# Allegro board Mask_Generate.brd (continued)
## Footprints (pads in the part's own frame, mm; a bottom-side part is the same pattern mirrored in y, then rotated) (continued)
NC06-4
  rect 1.27x0.635 smd: 1(-2.857,1.905) 2(-2.857,0.635) 3(-2.857,-0.635) 4(-2.857,-1.905) 5(2.857,-1.905) 6(2.857,-0.635) 7(2.857,0.635) 8(2.857,1.905)
QUA02BSMD
  rect 1.27x1.6 smd: 1(-1.27,0) 2(1.27,0)
SO08
  rect 1.27x0.635 smd: 1(-2.857,1.905) 2(-2.857,0.635) 3(-2.857,-0.635) 4(-2.857,-1.905) 5(2.857,-1.905) 6(2.857,-0.635) 7(2.857,0.635) 8(2.857,1.905)
SO14
  rect 1.27x0.635 smd: 1(-2.857,3.81) 2(-2.857,2.54) 3(-2.857,1.27) 4(-2.857,0) 5(-2.857,-1.27) 6(-2.857,-2.54) 7(-2.857,-3.81) 8(2.857,-3.81) 9(2.857,-2.54) 10(2.857,-1.27) 11(2.857,0) 12(2.857,1.27) 13(2.857,2.54) 14(2.857,3.81)
SO16B
  rect 1.27x0.635 smd: 1(-4.763,4.445) 2(-4.763,3.175) 3(-4.763,1.905) 4(-4.763,0.635) 5(-4.763,-0.635) 6(-4.763,-1.905) 7(-4.763,-3.175) 8(-4.763,-4.445) 9(4.763,-4.445) 10(4.763,-3.175) 11(4.763,-1.905) 12(4.763,-0.635) 13(4.763,0.635) 14(4.763,1.905) 15(4.763,3.175) 16(4.763,4.445)
SOT23B
  rect 0.508x0.432 smd: 1(-0.889,0.94) 2(-0.889,-0.94) 3(0.889,0)
SOT223-5
  rect 1.27x0.635 smd: 1(-2.477,1.27) 2(-2.477,-1.27) 3(2.477,1.27) 4(2.477,0) 5(2.477,-1.27)
SQU04B
  rect 1.27x0.635 smd: 1(-2.857,1.905) 2(-2.857,-1.905) 3(2.857,-1.905) 4(2.857,1.905)
TAJA
  rect 1.575x1.016 smd: 1(-1.968,0) 2(1.968,0)
TAJC
  rect 2.032x2.032 smd: 1(-2.223,0) 2(2.223,0)
TQFP64D
  rect 0.305x0.914 smd: 1(-0.4,7.429) 2(-1.2,7.429) 3(-2,7.429) 4(-2.8,7.429) 5(-3.6,7.429) 6(-4.401,7.429) 7(-5.201,7.429) 8(-6.001,7.429) 25(-6.001,-7.429) 26(-5.201,-7.429) 27(-4.401,-7.429) 28(-3.6,-7.429) 29(-2.8,-7.429) 30(-2,-7.429) 31(-1.2,-7.429) 32(-0.4,-7.429) 33(0.4,-7.429) 34(1.2,-7.429) 35(2,-7.429) 36(2.8,-7.429) 37(3.6,-7.429) 38(4.401,-7.429) 39(5.201,-7.429) 40(6.001,-7.429) 57(6.001,7.429) 58(5.201,7.429) 59(4.401,7.429) 60(3.6,7.429) 61(2.8,7.429) 62(2,7.429) 63(1.2,7.429) 64(0.4,7.429)
  rect 0.914x0.305 smd: 9(-7.429,6.001) 10(-7.429,5.201) 11(-7.429,4.401) 12(-7.429,3.6) 13(-7.429,2.8) 14(-7.429,2) 15(-7.429,1.2) 16(-7.429,0.4) 17(-7.429,-0.4) 18(-7.429,-1.2) 19(-7.429,-2) 20(-7.429,-2.8) 21(-7.429,-3.6) 22(-7.429,-4.401) 23(-7.429,-5.201) 24(-7.429,-6.001) 41(7.429,-6.001) 42(7.429,-5.201) 43(7.429,-4.401) 44(7.429,-3.6) 45(7.429,-2.8) 46(7.429,-2) 47(7.429,-1.2) 48(7.429,-0.4) 49(7.429,0.4) 50(7.429,1.2) 51(7.429,2) 52(7.429,2.8) 53(7.429,3.6) 54(7.429,4.401) 55(7.429,5.201) 56(7.429,6.001)
TSSOP56A
  rect 1.651x0.406 smd: 1(-5.639,9.601) 2(-5.639,8.801) 3(-5.639,8.001) 4(-5.639,7.201) 5(-5.639,6.401) 6(-5.639,5.601) 7(-5.639,4.801) 8(-5.639,4) 9(-5.639,3.2) 10(-5.639,2.4) 11(-5.639,1.6) 12(-5.639,0.8) 13(-5.639,0) 14(-5.639,-0.8) 15(-5.639,-1.6) 16(-5.639,-2.4) 17(-5.639,-3.2) 18(-5.639,-4) 19(-5.639,-4.801) 20(-5.639,-5.601) 21(-5.639,-6.401) 22(-5.639,-7.201) 23(-5.639,-8.001) 24(-5.639,-8.801) 25(-5.639,-9.601) 26(-5.639,-10.401) 27(-5.639,-11.201) 28(-5.639,-12.002) 29(5.639,-12.002) 30(5.639,-11.201) 31(5.639,-10.401) 32(5.639,-9.601) 33(5.639,-8.801) 34(5.639,-8.001) 35(5.639,-7.201) 36(5.639,-6.401) 37(5.639,-5.601) 38(5.639,-4.801) 39(5.639,-4) 40(5.639,-3.2) 41(5.639,-2.4) 42(5.639,-1.6) 43(5.639,-0.8) 44(5.639,0) 45(5.639,0.8) 46(5.639,1.6) 47(5.639,2.4) 48(5.639,3.2) 49(5.639,4) 50(5.639,4.801) 51(5.639,5.601) 52(5.639,6.401) 53(5.639,7.201) 54(5.639,8.001) 55(5.639,8.801) 56(5.639,9.601)
WWS02
  rect 1.118x1.829 smd: 1(-1.968,0) 2(1.968,0)

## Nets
GND: C61.2 C62.2 C63.2 C64.2 C65.2 C66.2 C67.2 C68.2 C69.2 C72.2 C73.2 C74.2 C75.2 C76.2 C77.2 C78.2 C79.2 C80.2 C81.2 C82.2 C83.2 C84.2 C85.2 C86.2 C87.2 C88.2 C89.2 C90.2 C91.2 C92.2 C93.2 C94.2 C95.2 C96.2 C97.2 C98.2 C99.2 C100.2 C101.2 C102.2 C103.2 C104.2 C105.2 C106.2 C107.2 C108.2 C109.2 C110.2 C111.2 C112.2 C113.2 C114.2 C115.2 C116.2 C117.2 C118.2 C119.2 C120.2 C121.2 C122.2 C123.2 C124.2 C125.2 C126.2 C127.2 C207.2 C208.2 C209.2 C210.2 C211.2 C212.2 C213.2 C214.2 C215.2 C216.2 C217.2 C219.2 C220.2 C221.2 C224.2 C225.2 C226.2 C227.2 C228.2 C229.2 C233.2 C234.2 C235.2 C236.2 C237.2 C238.2 C239.2 C240.2 C241.2 C242.2 C243.2 C244.2 C245.2 C246.2 C247.2 C248.2 C249.2 C250.2 C251.2 C252.2 C253.2 C254.2 C255.2 C256.2 C259.2 C260.2 C261.2 C262.2 C263.2 C264.2 C265.2 C266.2 C267.2 C268.2 C269.2 C270.2 C271.2 C272.2 C273.2 C274.2 C275.2 C276.2 C277.2 C278.2 C279.2 C280.2 C281.2 C282.2 C283.2 C284.2 C285.2 C286.2 C287.2 C288.2 C289.2 C290.2 C291.2 C292.2 C293.2 CF1.2(GND) CF2.2(GND) CF3.2(GND) CF4.3 CF5.2(GND) CF6.2(GND) CF7.2(GND) CF8.2(GND) CN2.3 CN2.11 CN2.18 CN2.26 CN2.34 CN2.42 CN2.50 CN2.58 CN2.66 CN2.74 CN2.81 CN2.89 CN2.93 CN2.97 CN2.100 CN2.107 CN2.116 CN2.119 CN2.124 CN2.129 CN2.132 CN2.139 CN2.140 CN2.145 CN2.149 CN2.152 CN2.159 CN2.160 CN2.169 CN2.176 CN2.177 CN2.181 CN2.182 CN2.183 CN4.2 CN4.3(VSS_DBL) CN5.1(VSS_VDL_FWSL_VCL) CN5.10 CN5.13 CN5.16 CN5.19 CN5.22 CN5.25 CN5.28 Q1.2(E) Q3.2(S) R57.2 R61.2 R62.1 R63.1 R64.2 R93.1 R94.1 R95.1 R99.2 R106.2 R107.2 R109.2 R134.1 R135.1 R136.2 R137.2 R138.1 R139.1 R144.2 R151.1 R154.2 R155.2 R156.2 R157.2 R158.2 R159.2 R160.2 R161.2 R162.2 R163.2 R164.2 R165.2 R166.2 R167.2 R168.2 R171.1 R172.1 R173.1 R176.1 R177.1 R182.1 R183.1 R186.2 R199.2 R201.2 R203.2 R205.2 R212.2 R214.2 R215.1 U2.4 U2.9 U2.15 U2.20 U2.27 U2.31 U2.36 U2.41 U2.47 U3.A3 U3.A7 U3.A11 U3.A15 U3.A19 U3.A23 U3.A27 U3.AA1 U3.AA4 U3.AA8 U3.AA29 U3.AB6 U3.AB9 U3.AB10 U3.AB12 U3.AB13 U3.AB14 U3.AB15 U3.AB16 U3.AB19 U3.AB22 U3.AC1 U3.AC4 U3.AC18 U3.AC20 U3.AC21 U3.AC23 U3.AC26 U3.AD6 U3.AD8 U3.AD10 U3.AD12 U3.AD14 U3.AD16 U3.AD19 U3.AD22 U3.AE1 U3.AE4 U3.AE18 U3.AE20 U3.AE29 U3.AF5 U3.AF7 U3.AF9 U3.AF11 U3.AF13 U3.AF15 U3.AF17 U3.AF19 U3.AF21 U3.AF25 U3.AG1 U3.AG18 U3.AG20 U3.AG22 U3.AH19 U3.AH21 U3.AH23 U3.AJ3 U3.AJ5 U3.AJ7 U3.AJ9 U3.AJ11 U3.AJ13 U3.AJ15 U3.AJ17 U3.AJ27 U3.D5 U3.D9 U3.D13 U3.D17 U3.D21 U3.E1 U3.E4 U3.E26 U3.E29 U3.F8 U3.F12 U3.F16 U3.F20 U3.F24 U3.G26 U3.H9 U3.H11 U3.H13 U3.H15 U3.H17 U3.H19 U3.H21 U3.J1 U3.J4 U3.J6 U3.J22 U3.J26 U3.J29 U3.K5 U3.K7 U3.K27 U3.L1 U3.L4 U3.L6 U3.L8 U3.L22 U3.L24 U3.L26 U3.M23 U3.N1 U3.N4 U3.N8 U3.N13 U3.N15 U3.N17 U3.N22 U3.N29 U3.P6 U3.P8 U3.P14 U3.P16 U3.R1 U3.R4 U3.R13 U3.R15 U3.R17 U3.R26 U3.T6 U3.T8 U3.T14 U3.T16 U3.T22 U3.U1 U3.U4 U3.U15 U3.U29 U3.V6 U3.V8 U3.V22 U3.W1 U3.W4 U3.W8 U3.W26 U3.Y6 U3.Y22 U4.2 U5.A1 U5.A23 U5.AC1 U5.AC23 U5.E5 U5.E7 U5.E9 U5.E11 U5.E13 U5.E15 U5.E19 U5.G5(VSS_9) U5.G19 U5.J5 U5.J19 U5.K12 U5.K13 U5.L5 U5.L12 U5.L13 U5.L19 U5.M12 U5.M13 U5.N5 U5.N12 U5.N13 U5.N19 U5.P12 U5.P13 U5.R5 U5.R19 U5.U5 U5.U19 U5.U22 U5.W5 U5.W9 U5.W11 U5.W14 U5.W16 U5.W17 U5.W19 U6.1 U6.4 U6.7 U7.1 U7.2 U7.4 U7.5 U7.7 U8.6 U8.7 U8.8 U8.16 U8.17 U8.20 U8.26 U8.32 U8.48 U8.64 U10.5 U11.5 U12.5
GND_AMCH: C70.2 C71.2 U3.U13 U3.U17
GND_DVI: CF4.1 ST1.15
GND_VID: C218.2 C223.2 C257.2 C258.2 CN6.1 CN6.2 JP1.2 R189.2 R190.2 R191.2 R215.2 ST1.C5 ST1.C6 U5.AA21 U5.AA22 U5.U20 U5.W20 U5.W22 U9.4 U9.13
A_CLKX1: C108.1 U2.2 XT1.1
A_CLKX2: C109.1 U2.3(XTAL_OUT) XT1.2
ABLUE: ST1.C3 U5.AA23 U9.3
ACON: R150.2 U5.P23
ACT_1: Q4.1 R196.2
ACT_2: Q4.3 R206.2
ACTIVITY: R151.2 R196.1 U5.P22
ADJ_LVD: C230.2 R202.2 R203.1 U10.4
ADJ_VDD1: C231.2 Q4.2(S) R199.1 R200.2 R201.1 U11.4
ADJ_VDD2: C232.2 R204.2 R205.1 U12.4
AGP_REF: C61.1 R210.1 U3.AA21
AGP_REFX: C243.1 R210.2 R211.2 R212.1 U5.D17
AGREEN: ST1.C2 U5.Y23 U9.5
AHSYNC: ST1.C4 U9.6
ARED: ST1.C1 U5.W23 U9.2
AVSYNC: ST1.8 U9.10(VSOUT)
BSEL0: R56.1 R100.2 U2.55
BSEL2: R107.1 U2.40
BSELX0: Q1.1 R56.2 R57.1
CHROMA: CN6.4 FB9.2
CK_14M: C126.1 R133.1 U5.T23
CK_14MX: R133.2 U2.56
CK_27: R174.1 U4.3
CK_AGP66: C115.1 R118.1 R144.1 U5.H20
CK_AGP66X: R118.2 U2.21
CK_CPLD: C118.1 R124.1
CK_CPLDX: R124.2 U2.6
CK_CPU+: R110.1 R134.2
CK_CPU-: R111.1 R135.2
CK_CPUX+: R110.2 U2.52
CK_CPUX-: R111.2 U2.51
CK_FPS: U5.Y9 U8.57
CK_FWH: R125.1
CK_FWHX: R125.2 U2.7
CK_ICH33: C117.1 R123.1
CK_ICH33X: R123.2 U2.5
CK_ICH48: C116.1 R122.1
CK_ICH48X: R122.2 U2.39
CK_ICH66: C114.1 R117.1
CK_ICH66X: R117.2 U2.35
CK_ITP+: R112.1 R136.1
CK_ITP-: R113.1 R137.1
CK_ITPX+: R112.2 U2.49
CK_ITPX-: R113.2 U2.48
CK_LAN: C121.1 R128.1
CK_LANX: R128.2 U2.12
CK_LPC0: C119.1 R126.1
CK_LPC0X: R126.2 U2.10
CK_LPC1: C120.1 R127.1
CK_LPC1X: R127.2 U2.11
CK_MCH66: C113.1 R116.1 U3.P22
CK_MCH66X: R116.2 U2.33
CK_MCH+: R114.1 R138.2 U3.J8
CK_MCH-: R115.1 R139.2 U3.K8
CK_MCHX+: R114.2 U2.45
CK_MCHX-: R115.2 U2.44
CK_MPCI: C122.1 R129.1
CK_MPCIX: R129.2 U2.13
CK_PAL: R174.2 U5.M21
CK_RES0: C112.1 R119.1
CK_RES1: C111.1 R120.1
CK_RES2: C110.1 R121.1
CK_RESX0: R119.2 U2.22
CK_RESX1: R120.2 U2.23
CK_RESX2: R121.2 U2.24
CK_SCK+<0>: CN2.16 U3.E14
CK_SCK+<1>: CN2.137 U3.J24
CK_SCK+<2>: CN2.76 U3.G6
CK_SCK+<3>: U3.G15
CK_SCK+<4>: U3.E24
CK_SCK+<5>: U3.H5
CK_SCK-<0>: CN2.17 U3.F15
CK_SCK-<1>: CN2.138 U3.G25
CK_SCK-<2>: CN2.75 U3.G7
CK_SCK-<3>: U3.G14
CK_SCK-<4>: U3.G24
CK_SCK-<5>: U3.F5
CK_SLOT1: C123.1 R130.1
CK_SLOT1X: R130.2 U2.16
CK_SLOT2: C124.1 R131.1
CK_SLOT2X: R131.2 U2.17
CK_SLOT3: C125.1 R132.1
CK_SLOT3X: R132.2 U2.18
COMPFLT1: C222.2 C223.1 FB6.2 FB7.1
CPU_STOP*: R101.2 U2.53
CVBS: FB7.2 JP1.1
DDC_CLK: CN5.6 ST1.6 U9.12
DDC_DAT: CN5.7 ST1.7 U9.15
DKEN: R183.2 U8.35
EN_LVD: C229.1 R193.2 R198.1 U10.1
EN_VDD1: R194.2 U11.1
EN_VDD2: R195.2 U12.1
ENA_VDL: Q3.1 U5.AA10
ENA_VDL*: Q2.4 Q3.3 R192.2
EXCKEN*: R170.2 U5.N20
EXT_SWING: R187.1 U8.19
FDATA0: U5.AC7 U8.63
FDATA1: U5.AB7 U8.62
FDATA2: U5.AA7 U8.61
FDATA3: U5.AC8 U8.60
FDATA4: U5.AB8 U8.59
FDATA5: U5.AC9 U8.58
FDATA6: U5.AB9 U8.55
FDATA7: U5.AA8 U8.54
FDATA8: U5.AA11 U8.53
FDATA9: U5.AB11 U8.52
FDATA10: U5.AC10 U8.51
FDATA11: U5.Y11 U8.50
FDATA12: U5.AA12 U8.47
FDATA13: U5.AB12 U8.46
FDATA14: U5.Y12 U8.45
FDATA15: U5.Y13 U8.44
FDATA16: U5.AA13 U8.43
FDATA17: U5.AB13 U8.42
FDATA18: U5.AA14 U8.41
FDATA19: U5.Y14 U8.40
FDATA20: U5.AC13 U8.39
FDATA21: U5.AC14 U8.38
FDATA22: U5.AB14 U8.37
FDATA23: U5.AC16 U8.36
FPDE: U5.Y8 U8.2
FPEN1: CN4.7 U5.AC6
FPHSYNC: U5.AA9 U8.4
FPVSYNC: U5.Y10 U8.5(VSYNC)
FS0: R108.2 U2.54
G_AD<0>: U3.R27 U5.A10
G_AD<1>: U3.R28 U5.B10
G_AD<2>: U3.T25 U5.A9
G_AD<3>: U3.R25 U5.C10
G_AD<4>: U3.T26 U5.B12
G_AD<5>: U3.T27 U5.B11
G_AD<6>: U3.U27 U5.C11
G_AD<7>: U3.U28 U5.C12
G_AD<8>: U3.V26 U5.C13
G_AD<9>: U3.V27 U5.B13
G_AD<10>: U3.T23 U5.B14
G_AD<11>: U3.U23 U5.C14
G_AD<12>: U3.T24 U5.A13
G_AD<13>: U3.U24 U5.B15
G_AD<14>: U3.U25 U5.A14
G_AD<15>: U3.V24 U5.C15
G_AD<16>: R145.1 U3.Y27 U5.A19
G_AD<17>: U3.Y26 U5.B19
G_AD<18>: U3.AA28 U5.A20
G_AD<19>: U3.AB25 U5.C18
G_AD<20>: U3.AB27 U5.B20
G_AD<21>: U3.AA27 U5.A21
G_AD<22>: U3.AB26 U5.C19
G_AD<23>: U3.Y23 U5.B21
G_AD<24>: U3.AB23 U5.C22
G_AD<25>: U3.AA24 U5.C23
G_AD<26>: U3.AA25 U5.D21
G_AD<27>: U3.AB24 U5.D22
G_AD<28>: U3.AC25 U5.D23
G_AD<29>: U3.AC24 U5.E21
G_AD<30>: U3.AC22 U5.E22
G_AD<31>: U3.AD24 U5.E23
G_ADSTB0+: U3.R24 U5.F20
G_ADSTB0-: U3.R23 U5.G20
G_ADSTB1+: U3.AC27 U5.E20
G_ADSTB1-: U3.AC28 U5.D20
G_BA0: R167.1 U5.L2
G_BA1: R168.1 U5.L3
G_BUSY*: R147.2 U5.B8
G_C/BE*<0>: U3.V25 U5.A15
G_C/BE*<1>: U3.V23 U5.B16
G_C/BE*<2>: U3.Y25 U5.A18
G_C/BE*<3>: U3.AA23 U5.C20
G_DEVSEL*: U3.W28 U5.C16
G_FRAME*: U3.Y24 U5.A17
G_GNT*: R60.1 U3.AH25 U5.F22
G_IDSEL: R145.2 U5.C21
G_IRDY*: U3.W27 U5.C17
G_MA0: R165.1 U5.L1
G_MA1: R164.1 U5.L4
G_MA2: R163.1 U5.M4
G_MA3: R162.1 U5.M3
G_MA4: R161.1 U5.P4
G_MA5: R160.1 U5.N3
G_MA6: R159.1 U5.M2
G_MA7: R158.1 U5.N2
G_MA8: R157.1 U5.J3
G_MA9: R156.1 U5.P3
G_MA10: R155.1 U5.R4
G_MA11: R154.1 U5.K4
G_PAR: U3.W25 U5.A16
G_PIPE*: U3.AF22 U5.C8
G_RBF*: U3.AE22 U5.C7
G_REQ*: U3.AG24 U5.F21
G_SBA<0>: U3.AH28 U5.D16
G_SBA<1>: U3.AH27 U5.D15
G_SBA<2>: U3.AG28 U5.D14
G_SBA<3>: U3.AG27 U5.D13
G_SBA<4>: U3.AE28 U5.D12
G_SBA<5>: U3.AE27 U5.D11
G_SBA<6>: U3.AE24 U5.D10
G_SBA<7>: U3.AE25 U5.D9
G_SBSTB+: U3.AF27 U5.D19
G_SBSTB-: U3.AF26 U5.D18
G_ST1X: Q1.3 R58.2 R59.1
G_ST<0>: R64.1 U3.AG25 U5.C9
G_ST<1>: R59.2 R61.1 U3.AF24 U5.B9
G_ST<2>: U3.AG26 U5.A8
G_STOP*: U3.W23 U5.B18
G_TEST0: R152.2 U5.T21
G_TEST1: R153.2 U5.T22
G_TRDY*: U3.W24 U5.B17
G_WBF*: R62.2 U3.AE23
GRCOMP: R63.2 U3.AD25
H_A*<3>: U3.T4
H_A*<4>: U3.T5
H_A*<5>: U3.T3
H_A*<6>: U3.U3
H_A*<7>: U3.R3
H_A*<8>: U3.P7
H_A*<9>: U3.R2
H_A*<10>: U3.P4
H_A*<11>: U3.R6
H_A*<12>: U3.P5
H_A*<13>: U3.P3
H_A*<14>: U3.N2
H_A*<15>: U3.N7
H_A*<16>: U3.N3
H_A*<17>: U3.K4
H_A*<18>: U3.M4
H_A*<19>: U3.M3
H_A*<20>: U3.L3
H_A*<21>: U3.L5
H_A*<22>: U3.K3
H_A*<23>: U3.J2
H_A*<24>: U3.M5
H_A*<25>: U3.J3
H_A*<26>: U3.L2
H_A*<27>: U3.H4
H_A*<28>: U3.N5
H_A*<29>: U3.G2
H_A*<30>: U3.M6
H_A*<31>: U3.L7
H_ADS*: U3.V3
H_ADSTB*<0>: U3.R5
H_ADSTB*<1>: U3.N6
H_BNR*: U3.W3
H_BPRI*: U3.Y7
H_BR0*: U3.V7
H_CPURST*: U3.AE17
H_D<0>: U3.AA2
H_D<1>: U3.AB5
H_D<2>: U3.AA5
H_D<3>: U3.AB3
H_D<4>: U3.AB4
H_D<5>: U3.AC5
H_D<6>: U3.AA3
H_D<7>: U3.AA6
H_D<8>: U3.AE3
H_D<9>: U3.AB7
H_D<10>: U3.AD7
H_D<11>: U3.AC7
H_D<12>: U3.AC6
H_D<13>: U3.AC3
H_D<14>: U3.AC8
H_D<15>: U3.AE2
H_D<16>: U3.AG5
H_D<17>: U3.AG2
H_D<18>: U3.AE8
H_D<19>: U3.AF6
H_D<20>: U3.AH2
H_D<21>: U3.AF3
H_D<22>: U3.AG3
H_D<23>: U3.AE5
H_D<24>: U3.AH7
H_D<25>: U3.AH3
H_D<26>: U3.AF4
H_D<27>: U3.AG8
H_D<28>: U3.AG7
H_D<29>: U3.AG6
H_D<30>: U3.AF8
H_D<31>: U3.AH5
H_D<32>: U3.AC11
H_D<33>: U3.AC12
H_D<34>: U3.AE9
H_D<35>: U3.AC9
H_D<36>: U3.AE10
H_D<37>: U3.AD9
H_D<38>: U3.AG9
H_D<39>: U3.AC10
H_D<40>: U3.AE12
H_D<41>: U3.AF10
H_D<42>: U3.AG11
H_D<43>: U3.AG10
H_D<44>: U3.AH11
H_D<45>: U3.AG12
H_D<46>: U3.AE13
H_D<47>: U3.AF12
H_D<48>: U3.AG13
H_D<49>: U3.AH13
H_D<50>: U3.AC14
H_D<51>: U3.AF14
H_D<52>: U3.AG14
H_D<53>: U3.AE14
H_D<54>: U3.AG15
H_D<55>: U3.AG16
H_D<56>: U3.AG17
H_D<57>: U3.AH15
H_D<58>: U3.AC17
H_D<59>: U3.AF16
H_D<60>: U3.AE15
H_D<61>: U3.AH17
H_D<62>: U3.AD17
H_D<63>: U3.AE16
H_DBI*<0>: U3.AD5
H_DBI*<1>: U3.AG4
H_DBI*<2>: U3.AH9
H_DBI*<3>: U3.AD15
H_DBSY*: U3.V5
H_DEFER*: U3.Y4
H_DRDY*: U3.V4
H_DSTBN*<0>: U3.AD4
H_DSTBN*<1>: U3.AE6
H_DSTBN*<2>: U3.AE11
H_DSTBN*<3>: U3.AC15
H_DSTBP*<0>: U3.AD3
H_DSTBP*<1>: U3.AE7
H_DSTBP*<2>: U3.AD11
H_DSTBP*<3>: U3.AC16
H_HI<0>: U3.P25
H_HI<1>: U3.P24
H_HI<2>: U3.N27
H_HI<3>: U3.P23
H_HI<4>: U3.M26
H_HI<5>: U3.M25
H_HI<6>: U3.L28
H_HI<7>: U3.L27
H_HI<8>: U3.M27
H_HI<9>: U3.N28
H_HI<10>: U3.M24
H_HISTB+: U3.N25
H_HISTB-: U3.N24
H_HIT*: U3.Y5
H_HITM*: U3.Y3
H_LOCK*: U3.W5
H_REQ*<0>: U3.U6
H_REQ*<1>: U3.T7
H_REQ*<2>: U3.R7
H_REQ*<3>: U3.U5
H_REQ*<4>: U3.U2
H_RS*<0>: U3.W2
H_RS*<1>: U3.W7
H_RS*<2>: U3.W6
H_TRDY*: U3.U7
HI_REF: C63.1 U3.P26
HLRCOMP: R97.1 U3.P27
HOTPLUG: ST1.16 U8.9
HRCOMP0: R95.2 U3.AC2
HRCOMP1: R94.2 U3.AC13
HSWNG: C62.1 R92.1 R93.2 U3.AA7 U3.AD13
HVREF_MCH: C74.1 R98.2 R99.1 U3.AB11 U3.AB17 U3.M7 U3.R8 U3.Y8
INT_PIRQA*: U5.G22
IREF_CK: R109.1 U2.42
IREF_VGA1: R173.2 U5.Y22
IREF_VGA2: R172.2 U5.U23
ISEL: R182.2 U8.13
ITV_C: FB9.1 R190.1 U5.V22
ITV_CVBS: C218.1 C222.1 FB6.1 R189.1 U5.V23
ITV_HSYNC: U5.P20 U6.2
ITV_HSYNCX: U6.3 U9.7
ITV_SCL: U5.R23 U9.11
ITV_SDA: U5.R22 U9.14
ITV_VSYNC: U5.P21 U6.5
ITV_VSYNCX: U6.6 U9.9
ITV_Y: FB8.1 R191.1 U5.V21
LUMA: CN6.3(Y) FB8.2
M_D<0>: CN2.2 RN16.7
M_D<1>: CN2.4 RN16.5
M_D<2>: CN2.6 RN16.3
M_D<3>: CN2.8 RN16.1
M_D<4>: CN2.94 RN15.7
M_D<5>: CN2.95 RN15.5
M_D<6>: CN2.98 RN15.3
M_D<7>: CN2.99 RN15.1
M_D<8>: CN2.12 RN14.7
M_D<9>: CN2.13 RN14.5
M_D<10>: CN2.19 RN14.3
M_D<11>: CN2.20 RN14.1
M_D<12>: CN2.105 RN13.7
M_D<13>: CN2.106 RN13.5
M_D<14>: CN2.109 RN13.3
M_D<15>: CN2.110 RN13.1
M_D<16>: CN2.23 RN12.7
M_D<17>: CN2.24 RN12.5
M_D<18>: CN2.28 RN12.3
M_D<19>: CN2.31 RN12.1
M_D<20>: CN2.114 RN11.7
M_D<21>: CN2.117 RN11.5
M_D<22>: CN2.121 RN11.3
M_D<23>: CN2.123 RN11.1
M_D<24>: CN2.33 RN10.7
M_D<25>: CN2.35 RN10.5
M_D<26>: CN2.39 RN10.3
M_D<27>: CN2.40 RN10.1
M_D<28>: CN2.126 RN9.7
M_D<29>: CN2.127 RN9.5
M_D<30>: CN2.131 RN9.3
M_D<31>: CN2.133 RN9.1
M_D<32>: CN2.53 RN8.7
M_D<33>: CN2.55 RN8.5
M_D<34>: CN2.57 RN8.3
M_D<35>: CN2.60 RN8.1
M_D<36>: CN2.146 RN7.7
M_D<37>: CN2.147 RN7.5
M_D<38>: CN2.150 RN7.3
M_D<39>: CN2.151 RN7.1
M_D<40>: CN2.61 RN6.7
M_D<41>: CN2.64 RN6.5
M_D<42>: CN2.68 RN6.3
M_D<43>: CN2.69 RN6.1
M_D<44>: CN2.153 RN5.7
M_D<45>: CN2.155 RN5.5
M_D<46>: CN2.161 RN5.3
M_D<47>: CN2.162 RN5.1
M_D<48>: CN2.72 RN4.7
M_D<49>: CN2.73 RN4.5
M_D<50>: CN2.79 RN4.3
M_D<51>: CN2.80 RN4.1
M_D<52>: CN2.165 RN3.7
M_D<53>: CN2.166 RN3.5
M_D<54>: CN2.170 RN3.3
M_D<55>: CN2.171 RN3.1
M_D<56>: CN2.83 RN2.7
M_D<57>: CN2.84 RN2.5
M_D<58>: CN2.87 RN2.3
M_D<59>: CN2.88 RN2.1
M_D<60>: CN2.174 RN1.7
M_D<61>: CN2.175 RN1.5
M_D<62>: CN2.178 RN1.3
M_D<63>: CN2.179 RN1.1
M_DX0: RN16.8(PIN2) U3.G28
M_DX1: RN16.6 U3.F27
M_DX2: RN16.4 U3.C28
M_DX3: RN16.2 U3.E28
M_DX4: RN15.8(PIN2) U3.H25
M_DX5: RN15.6 U3.G27
M_DX6: RN15.4 U3.F25
M_DX7: RN15.2 U3.B28
M_DX8: RN14.8(PIN2) U3.E27
M_DX9: RN14.6 U3.C27
M_DX10: RN14.4 U3.B25
M_DX11: RN14.2 U3.C25
M_DX12: RN13.8(PIN2) U3.B27
M_DX13: RN13.6 U3.D27
M_DX14: RN13.4 U3.D26
M_DX15: RN13.2 U3.E25
M_DX16: RN12.8(PIN2) U3.D24
M_DX17: RN12.6 U3.E23
M_DX18: RN12.4 U3.C22
M_DX19: RN12.2 U3.E21
M_DX20: RN11.8(PIN2) U3.C24
M_DX21: RN11.6 U3.B23
M_DX22: RN11.4 U3.D22
M_DX23: RN11.2 U3.B21
M_DX24: RN10.8(PIN2) U3.C21
M_DX25: RN10.6 U3.D20
M_DX26: RN10.4 U3.C19
M_DX27: RN10.2 U3.D18
M_DX28: RN9.8(PIN2) U3.C20
M_DX29: RN9.6 U3.E19
M_DX30: RN9.4 U3.C18
M_DX31: RN9.2 U3.E17
M_DX32: RN8.8(PIN2) U3.E13
M_DX33: RN8.6 U3.C12
M_DX34: RN8.4 U3.B11
M_DX35: RN8.2 U3.C10
M_DX36: RN7.8(PIN2) U3.B13
M_DX37: RN7.6 U3.C13
M_DX38: RN7.4 U3.C11
M_DX39: RN7.2 U3.D10
M_DX40: RN6.8(PIN2) U3.E10
M_DX41: RN6.6 U3.C9
M_DX42: RN6.4 U3.D8
M_DX43: RN6.2 U3.E8
M_DX44: RN5.8(PIN2) U3.E11
M_DX45: RN5.6 U3.B9
M_DX46: RN5.4 U3.B7
M_DX47: RN5.2 U3.C7
M_DX48: RN4.8(PIN2) U3.C6
M_DX49: RN4.6 U3.D6
M_DX50: RN4.4 U3.D4
M_DX51: RN4.2 U3.B3
M_DX52: RN3.8(PIN2) U3.E6
M_DX53: RN3.6 U3.B5
M_DX54: RN3.4 U3.C4
M_DX55: RN3.2 U3.E5
M_DX56: RN2.8(PIN2) U3.C3
M_DX57: RN2.6 U3.D3
M_DX58: RN2.4 U3.F4
M_DX59: RN2.2 U3.F3
M_DX60: RN1.8(PIN2) U3.B2
M_DX61: RN1.6 U3.C2
M_DX62: RN1.4 U3.E2
M_DX63: RN1.2 U3.G5
M_SBS0: CN2.59 R88.2
M_SBS1: CN2.52 R87.2
M_SBSX0: R88.1 U3.G12
M_SBSX1: R87.1 U3.G13
M_SCAS*: CN2.65 R90.2
M_SCASX*: R90.1 U3.G8
M_SCB<0>: CN2.44 RN18.7
M_SCB<1>: CN2.45 RN18.5
M_SCB<2>: CN2.49 RN18.3
M_SCB<3>: CN2.51 RN18.1
M_SCB<4>: CN2.134 RN17.7
M_SCB<5>: CN2.135 RN17.5
M_SCB<6>: CN2.142 RN17.3
M_SCB<7>: CN2.144 RN17.1
M_SCBX0: RN18.8(PIN2) U3.C16
M_SCBX1: RN18.6 U3.D16
M_SCBX2: RN18.4 U3.B15
M_SCBX3: RN18.2 U3.C14
M_SCBX4: RN17.8(PIN2) U3.B17
M_SCBX5: RN17.6 U3.C17
M_SCBX6: RN17.4 U3.C15
M_SCBX7: RN17.2 U3.D14
M_SCKE<0>: CN2.21 U3.G23
M_SCKE<1>: CN2.111 U3.E22
M_SCKE<2>: U3.H23
M_SCKE<3>: U3.F23
M_SCS*<0>: CN2.157 U3.E9
M_SCS*<1>: CN2.158 U3.F7
M_SCS*<2>: U3.F9
M_SCS*<3>: U3.E7
M_SDQS<0>: CN2.5 R86.2
M_SDQS<1>: CN2.14 R85.2
M_SDQS<2>: CN2.25 R84.2
M_SDQS<3>: CN2.36 R83.2
M_SDQS<4>: CN2.56 R82.2
M_SDQS<5>: CN2.67 R81.2
M_SDQS<6>: CN2.78 R80.2
M_SDQS<7>: CN2.86 R79.2
M_SDQS<8>: CN2.47 R78.2
M_SDQSX0: R86.1 U3.F26
M_SDQSX1: R85.1 U3.C26
M_SDQSX2: R84.1 U3.C23
M_SDQSX3: R83.1 U3.B19
M_SDQSX4: R82.1 U3.D12
M_SDQSX5: R81.1 U3.C8
M_SDQSX6: R80.1 U3.C5
M_SDQSX7: R79.1 U3.E3
M_SDQSX8: R78.1 U3.E15
M_SMA<0>: CN2.48 R77.2
M_SMA<1>: CN2.43 R76.2
M_SMA<2>: CN2.41 R75.2
M_SMA<3>: CN2.130 R74.2
M_SMA<4>: CN2.37 R73.2
M_SMA<5>: CN2.32 R72.2
M_SMA<6>: CN2.125 R71.2
M_SMA<7>: CN2.29 R70.2
M_SMA<8>: CN2.122 R69.2
M_SMA<9>: CN2.27 R68.2
M_SMA<10>: CN2.141 R67.2
M_SMA<11>: CN2.118 R66.2
M_SMA<12>: CN2.115 R65.2
M_SMAX0: R77.1 U3.E12
M_SMAX1: R76.1 U3.F17
M_SMAX2: R75.1 U3.E16
M_SMAX3: R74.1 U3.G18
M_SMAX4: R73.1 U3.G19
M_SMAX5: R72.1 U3.E18
M_SMAX6: R71.1 U3.F19
M_SMAX7: R70.1 U3.G21
M_SMAX8: R69.1 U3.G20
M_SMAX9: R68.1 U3.F21
M_SMAX10: R67.1 U3.F13
M_SMAX11: R66.1 U3.E20
M_SMAX12: R65.1 U3.G22
M_SRAS*: CN2.154 R89.2
M_SRASX*: R89.1 U3.F11
M_SWE*: CN2.63 R91.2
M_SWEX*: R91.1 U3.G11
MSEN: R184.2 R185.2 U8.11
MSENX: R184.1 U5.R21
MULTISEL: R105.1 R106.1 U2.43
MVREF: C242.1 R213.2 R214.1 U5.G4
P_RST0*: U3.J27
P_RST1*: U5.G21
PCI_STOP*: R102.2 U2.34
PDOWN*: R149.2 U5.N21
PGOOD408*: R104.2 U2.28
PME_VGA*: R146.2 U5.B7
PWM_BL: CN4.6
PWRDWN*: R103.2 U2.25
RCVEN*: U3.G3 U3.H3
SET_SD: R166.1 U5.D8
SHIELD: CF4.2(GND) CN6.5 CN6.6 CN6.7 ST1.3 ST1.11 ST1.19 ST1.22 ST1.DR1 ST1.DR2
SI_PWRDN*: U5.R20 U8.10
SIL_BSEL: R175.2 U8.15
SIL_DSEL: R176.2 U8.14
SIL_RSVD: R177.2 U8.34
SMBISOC: CN2.92 U2.30
SMBISOD: CN2.91 U2.29
SMRCOMP: C73.1 R96.1 U3.J28
SPNLCLKI: R171.2 U5.AB21
ST27*: R169.2 U4.1
STP_AGP*: R148.2 U5.A7
TMDS0+: L15.4 U8.25
TMDS0-: L15.1 U8.24
TMDS0C+: L15.3 ST1.18
TMDS0C-: L15.2 ST1.17
TMDS1+: L14.4 U8.28
TMDS1-: L14.1 U8.27
TMDS1C+: L14.3 ST1.10
TMDS1C-: L14.2 ST1.9
TMDS2+: L13.4 U8.31
TMDS2-: L13.1 U8.30
TMDS2C+: L13.3 ST1.2
TMDS2C-: L13.2 ST1.1
TMDSCLK+: L16.4 U8.22
TMDSCLK-: L16.1 U8.21
TMDSCLKC+: L16.3 ST1.23
TMDSCLKC-: L16.2 ST1.24
TX0+: L11.4 U5.AC18
TX0-: L11.1 U5.AB18
TX0C+: CN5.9 L11.3
TX0C-: CN5.8 L11.2
TX1+: L10.4 U5.AA19
TX1-: L10.1 U5.Y19
TX1C+: CN5.12 L10.3
TX1C-: CN5.11 L10.2
TX2+: L9.4 U5.AA20
TX2-: L9.1 U5.Y20
TX2C+: CN5.15 L9.3
TX2C-: CN5.14 L9.2
TX3+: R181.1 U5.AC20
TX3-: R180.1 U5.AB20
TX3_4+: L7.4 R179.2 R181.2
TX3_4-: L7.1 R178.2 R180.2
TX3_4C+: CN5.21 L7.3
TX3_4C-: CN5.20 L7.2
TX4+: R179.1 U5.AC17
TX4-: R178.1 U5.AB17
TX5+: L6.4 U5.AA18
TX5-: L6.1 U5.Y18
TX5C+: CN5.24 L6.3
TX5C-: CN5.23 L6.2
TX6+: L5.4 U5.AA17
TX6-: L5.1 U5.Y17
TX6C+: CN5.27 L5.3
TX6C-: CN5.26 L5.2
TXCLK1+: L12.4 U5.AB19
TXCLK1-: L12.1 U5.AC19
TXCLK1C+: CN5.18 L12.3
TXCLK1C-: CN5.17 L12.2
TXCLK2+: L8.4 U5.Y16
TXCLK2-: L8.1 U5.AA16
TXCLK2C+: CN5.30 L8.3
TXCLK2C-: CN5.29 L8.2
V_1V5: C76.1 C78.1 C80.1 C83.1 C86.1 C89.1 C92.1 C94.1 C95.1 C96.1 FB14.1 L3.1 L4.1 R58.1 R60.2 R211.1 U3.AA22 U3.AA26 U3.AB21 U3.AC29 U3.AD21 U3.AD23 U3.AE26 U3.AF23 U3.AG29 U3.AJ25 U3.N14 U3.N16 U3.P13 U3.P15 U3.P17 U3.R14 U3.R16 U3.R22 U3.R29 U3.T15 U3.U14 U3.U16 U3.U22 U3.U26 U3.W22 U3.W29
V_1V5A1: C70.1 L3.2 U3.T17
V_1V5A2: C71.1 L4.2 U3.T13
V_1V8: C81.1 C87.1 C90.1 C93.1 R97.2 U3.L25 U3.L29 U3.M22 U3.N23 U3.N26
V_2V0_2V5: C231.1 C234.1 C235.1 CF6.1 R198.2 R200.1 R206.1 U11.3(VOUT)
V_2V5_LVD: C230.1 C233.1 R202.1 R207.1 R208.1 R209.1 U10.3(VOUT)
V_2V5_LVD1: FB15.1 FB16.1 FB17.1 R208.2
V_2V5_LVD2: FB18.1 R209.2
V_2V5_VDD: C232.1 C236.1 C237.1 C238.1 CF7.1 CF8.1 R197.2 R204.1 R207.2 U12.3(VOUT)
V_3V3: C97.1 C98.1 C207.1 C219.1 C220.1 C221.1 C226.1 C227.1 C228.1 CF2.3 FB1.1 FB2.1 FB3.2 FB4.2 FB5.2 FB10.1 FB11.1 FB12.1 FB13.1 Q2.1 Q2.2 Q2.3(S3) R101.1 R102.1 R103.1 R104.1 R105.2 R146.1 R147.1 R148.1 R149.1 R150.1 R169.1 R170.1 R175.1 R185.1 R188.2 R192.1 R193.1 R194.1 R195.1 R197.1 U4.4(VCC) U10.2 U11.2 U12.2
V_5DVI: C225.1 CF5.3 F1.1
V_5DVIF: C224.1 CF5.1 ST1.14
V_5V0: D1.1 F1.2 R152.1 R153.1
V_5V0VGA: D1.3 U6.14 U9.1 U9.8 U9.16
V_12V0: CF1.3
V_AVCC1: C209.1 C213.1 C216.1 FB4.1 R187.2 U8.23 U8.29
V_AVDD: C257.1 FB10.2 U5.W21
V_BLI: CF1.1 CN4.1
V_CLK: C99.1 C100.1 C101.1 C102.1 C104.1 C106.1 FB1.2 R100.1 R108.1 U2.8 U2.14 U2.19 U2.32 U2.46 U2.50
V_CLKA: C103.1 C105.1 C107.1 FB2.2 U2.1 U2.26 U2.37
V_CORE: C64.1 C65.1 C66.1 C68.1 C69.1 C72.1 R92.2 R98.1 U3.AA9 U3.AB8 U3.AB18 U3.AB20 U3.AC19 U3.AD18 U3.AD20 U3.AE19 U3.AE21 U3.AF18 U3.AF20 U3.AG19(VTT<9>) U3.AG21 U3.AG23 U3.AJ19 U3.AJ21 U3.AJ23 U3.M8 U3.U8
V_CVDD: C265.1 C276.1 FB18.2 U5.U21
V_DBL: CF2.1 CN4.4
V_DDR: C75.1 C77.1 C79.1 C82.1 C84.1 C85.1 C88.1 C91.1 CN2.7 CN2.15 CN2.22 CN2.30 CN2.38 CN2.46 CN2.54 CN2.62 CN2.70 CN2.77 CN2.85 CN2.96 CN2.104 CN2.108 CN2.112 CN2.120 CN2.128 CN2.136 CN2.143 CN2.148 CN2.156 CN2.164 CN2.168 CN2.172 CN2.180 CN2.184 U3.A5 U3.A9 U3.A13 U3.A17 U3.A21 U3.A25 U3.C1 U3.C29 U3.D7 U3.D11 U3.D15 U3.D19 U3.D23 U3.D25 U3.F6 U3.F10 U3.F14 U3.F18 U3.F22 U3.G1 U3.G4 U3.G29 U3.H8 U3.H10 U3.H12 U3.H14 U3.H16 U3.H18 U3.H20 U3.H22 U3.H24 U3.J5 U3.J7 U3.K6 U3.K22 U3.K24 U3.K26 U3.L23
V_DDRREF: C67.1 C127.1 CN2.1 U3.J9 U3.J21
V_DDRVTT: R96.2
V_DL_CL: CF3.3 Q2.5 Q2.6 Q2.7 Q2.8
V_DL_CLF: CF3.1 CN5.2 CN5.3 CN5.4
V_FPVDD: C259.1 C271.1 FB12.2 U5.W8 U5.W10 U5.W12
V_HVDD: C261.1 C272.1 C282.1 C288.1 FB14.2 U5.E12 U5.E14 U5.E17 U5.F19 U5.K19
V_LVDD1: C262.1 C273.1 FB15.2 U5.W18
V_LVDD2: C263.1 C274.1 FB16.2 U5.W13
V_PLLVDD: C264.1 C275.1 FB17.2 U5.W15
V_PVCC1: C210.1 C214.1 C217.1 FB5.1 U8.18 U8.49
V_TVDD: C258.1 FB11.2 U5.V20
V_VCC1: C208.1 C212.1 C215.1 FB3.1 U8.1 U8.12 U8.33
V_VDD1: C239.1 C244.1 C247.1 C252.1 C266.1 C277.1 C283.1 C289.1 CF6.3 U5.AB22 U5.AC12 U5.AC22 U5.E16 U5.K14 U5.L14 U5.M14 U5.N14 U5.P14 U5.T19 U5.V19
V_VDD2: C240.1 C245.1 C246.1 C248.1 C249.1 C253.1 C254.1 C267.1 C268.1 C278.1 C279.1 C284.1 C285.1 C290.1 C291.1 CF7.3 R213.1 U5.A2 U5.A12 U5.A22 U5.AB1 U5.AC2 U5.AC11 U5.B1 U5.B23 U5.E6 U5.E10 U5.E18 U5.H5 U5.H19 U5.M1 U5.M5 U5.M11 U5.N10 U5.N11 U5.P10 U5.P11 U5.P19 U5.T5 U5.W6
V_VDD3: C241.1 C250.1 C251.1 C255.1 C256.1 C269.1 C270.1 C280.1 C281.1 C286.1 C287.1 C292.1 C293.1 CF8.3 U5.A11 U5.AB2 U5.B2 U5.E8 U5.F5 U5.K5 U5.K10 U5.K11 U5.L10 U5.L11 U5.M10 U5.N1 U5.P5 U5.V5 U5.Y5
V_VPVDD: C260.1 FB13.2 U5.M19
V_VREF_SII: C211.1 R186.1 R188.1 U8.3

Pads without a net: C1 1 2; CN2 9 10 71 82 90 101 102 103 113 163 167 173; CN4 5; CN5 5; D1 2; ST1 4 5 12 13 20 21; U2 38; U3 AD26 AD27 G9 G10 G16 G17 H6 H7 H26 H27 J23 J25 K23 K25; U5 A3 A4 A5 A6 AA1 AA2 AA3 AA4 AA5 AA6 AA15 AB3 AB4 AB5 AB6 AB10 AB15 AB16 AB23 AC3 AC4 AC5 AC15 AC21 B3 B4 B5 B6 B22 C1 C2 C3 C4 C5 C6 D1 D2 D3 D4 D5 D6 D7 E1 E2 E3 E4 F1 F2 F3 F4 F23 G1 G2 G3 G23 H1 H2 H3 H4 H21 H22 H23 J1 J2 J4 J20 J21 J22 J23 K1 K2 K3 K20 K21 K22 K23 L20 L21 L22 L23 M20 M22 M23 N4 N22 N23 P1 P2 R1 R2 R3 T1 T2 T3 T4 T20 U1 U2 U3 U4 V1 V2 V3 V4 W1 W2 W3 W4 W7 Y1 Y2 Y3 Y4 Y6 Y7 Y15 Y21; U6 8 9 10 11 12 13; U7 3 6 8 9 10 11 12 13 14; U8 56

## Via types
v1: diameter 0.508, hole 0.33, TOP to BOTTOM, 43 vias

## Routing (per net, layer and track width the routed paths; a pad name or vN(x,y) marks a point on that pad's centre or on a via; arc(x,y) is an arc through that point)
G_AD<0>: length 79.7
  TOP w0.127: v1(57.75,141.54) U5.A10 ; v1(116.14,151.54) U3.R27
  INT3 w0.127: v1(58.17,136.65) 64.77,136.65 65.02,136.4 85.48,136.4 85.67,136.59 v1(89.41,136.59) ; v1(116.14,151.54) 115.69,151.09 114.95,151.09 114.91,151.13 100.71,151.13 100.33,151.51 92.99,151.51 92.22,150.75 v1(89.22,150.75)
  INT4 w0.127: v1(57.75,141.54) 57.75,137.07 v1(58.17,136.65)
  BOTTOM w0.127: v1(89.41,136.59) 89.41,149.87 89.22,150.06 v1(89.22,150.75)
G_AD<1>: length 78.4
  TOP w0.127: v1(115.14,151.54) U3.R28 ; v1(57.75,142.54) U5.B10
  INT3 w0.127: v1(115.14,151.54) 100.71,151.54 100.48,151.76 92.88,151.76 92.37,151.26 v1(88.77,151.26) ; v1(58.8,137.29) 64.9,137.29 65.28,136.91 85.36,136.91 85.48,137.03 v1(88.9,137.03)
  INT4 w0.127: v1(57.75,142.54) 58.3,141.98 58.3,141.35 58.8,140.85 v1(58.8,137.29)
  BOTTOM w0.127: v1(88.77,151.26) 88.77,149.87 88.9,149.75 v1(88.9,137.03)
G_AD<2>: length 77
  TOP w0.127: v1(58.75,141.54) U5.A9 ; v1(118.14,153.54) U3.T25
  INT3 w0.127: v1(87.44,152.78) 92.52,152.78 92.77,152.53 100.58,152.53 100.71,152.65 117.25,152.65 v1(118.14,153.54) ; v1(87.38,138.37) 85.3,138.37 85.24,138.43 v1(63.37,138.43)
  INT4 w0.127: v1(58.75,141.54) 60.27,141.54 v1(63.37,138.43)
  BOTTOM w0.127: v1(87.44,152.78) 87.44,149.69 87.38,149.63 v1(87.38,138.37)
G_AD<3>: length 95.4
  TOP w0.127: v1(57.75,143.54) U5.C10 ; v1(118.14,151.54) U3.R25
  INT3 w0.127: v1(57.75,143.54) 52.86,143.54 51.69,142.37 51.69,137.54 53.09,136.14 64.9,136.14 65.15,135.89 85.6,135.89 85.85,136.14 v1(89.92,136.14) ; v1(89.66,150.24) 92.08,150.24 93.09,151.26 100.2,151.26 100.71,150.75 117.35,150.75 v1(118.14,151.54)
  BOTTOM w0.127: v1(89.92,136.14) 89.92,149.45 89.66,149.7 v1(89.66,150.24)
G_AD<4>: length 82.4
  TOP w0.127: v1(54.75,142.54) U5.B12 ; v1(117.14,153.54) U3.T26
  INT3 w0.127: v1(54.75,139.2) 55.11,139.2 55.5,138.81 63.13,138.81 63.19,138.87 63.56,138.87 63.62,138.81 64.9,138.81 65.02,138.94 85.36,138.94 85.48,138.81 v1(86.87,138.81) ; v1(87,153.29) 92.37,153.29 92.88,152.78 100.4,152.78 100.71,153.09 116.69,153.09 v1(117.14,153.54)
  INT4 w0.127: v1(54.75,142.54) v1(54.75,139.2)
  BOTTOM w0.127: v1(86.87,138.81) 86.87,149.75 87,149.87 v1(87,153.29)
G_AD<5>: length 79
  TOP w0.127: v1(56.75,142.54) U5.B11 ; v1(116.14,153.54) U3.T27
  INT3 w0.127: v1(56.75,139.42) 64.87,139.42 64.9,139.45 85.48,139.45 85.67,139.26 v1(86.36,139.26) ; v1(86.55,153.8) 92.22,153.8 92.99,153.03 100.21,153.03 100.71,153.54 v1(116.14,153.54)
  INT4 w0.127: v1(56.75,142.54) v1(56.75,139.42)
  BOTTOM w0.127: v1(86.36,139.26) 86.36,149.87 86.55,150.06 v1(86.55,153.8)
G_AD<10>: length 89.7
  TOP w0.127: v1(52.75,142.54) U5.B14 ; v1(120.14,153.54) U3.T23
  INT3 w0.127: v1(120.14,153.54) 118.62,152.02 114.94,152.02 114.81,151.89 100.71,151.89 100.58,152.02 92.77,152.02 92.52,151.76 v1(88.33,151.76) ; v1(52.7,137.67) 58.55,137.67 58.62,137.73 58.99,137.73 59.05,137.67 64.9,137.67 65.15,137.41 85.24,137.41 85.3,137.48 v1(88.39,137.48)
  INT4 w0.127: v1(52.7,137.67) 52.07,138.3 52.07,141.86 52.75,142.53 v1(52.75,142.54)
  BOTTOM w0.127: v1(88.33,151.76) 88.33,149.69 88.39,149.63 v1(88.39,137.48)
G_AD<12>: length 86.5
  TOP w0.127: v1(53.75,141.54) U5.A13 ; v1(119.14,153.54) U3.T24
  INT3 w0.127: v1(52.7,138.56) 53.21,138.56 53.59,138.18 63,138.18 63.19,137.99 63.56,137.99 63.75,138.18 65.02,138.18 65.28,137.92 v1(87.88,137.92) ; v1(87.88,152.27) 117.87,152.27 v1(119.14,153.54)
  INT4 w0.127: v1(53.75,141.54) 53.75,140.36 52.7,139.32 v1(52.7,138.56)
  BOTTOM w0.127: v1(87.88,152.27) v1(87.88,137.92)
G_AD<14>: length 84
  TOP w0.127: v1(118.14,154.54) U3.U25 ; v1(52.75,141.54) U5.A14
  INT3 w0.127: v1(86.11,154.3) 92.08,154.3 93.09,153.29 100.08,153.29 100.71,153.92 115.9,153.92 116.02,154.05 117.65,154.05 v1(118.14,154.54) ; v1(85.85,139.7) 85.31,139.7 85.06,139.95 65.06,139.95 64.9,139.79 57.01,139.79 56.93,139.87 56.56,139.87 56.48,139.79 53.04,139.79 52.75,140.08 v1(52.75,141.54)
  BOTTOM w0.127: v1(86.11,154.3) 86.11,150.24 85.85,149.99 v1(85.85,139.7)
SMBISOC: length 165.3
  TOP w0.127: U2.30 133.12,192 152.4,172.72 191.13,172.72 255.37,108.48 256.25,108.48 257.01,107.72 257.64,107.72 258.41,108.48 CN2.92

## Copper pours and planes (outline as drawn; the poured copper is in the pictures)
GND on PLA5: 2.54,2.54 2.54,251.46 16.38,251.46 16.38,244.6 8.13,244.6 8.13,231.01 24.64,231.01 24.64,199.26 29.08,199.26 29.08,168.4 25.27,168.4 25.27,164.59 14.48,164.59 14.48,158.62 22.99,158.62 22.99,161.16 31.62,161.16 31.62,153.54 36.32,153.54 36.32,157.35 48.39,157.35 48.39,163.96 35.05,163.96 35.05,199.26 38.86,199.26 38.86,231.65 77.6,231.65 77.6,236.09 83.31,236.09 83.31,251.46 276.86,251.46 276.86,2.54 ; 2 cut-outs
GND on PLA8: 2.54,2.54 2.54,251.46 16.38,251.46 16.38,236.09 24.26,236.09 24.26,243.08 41.78,243.08 41.78,236.73 48.13,236.73 48.13,234.19 50.93,234.19 50.93,237.36 54.74,237.36 54.74,243.71 61.47,243.71 61.47,237.36 68.07,237.36 68.07,243.71 77.34,243.71 77.34,236.09 83.31,236.09 83.31,251.46 276.86,251.46 276.86,2.54
GND_AMCH on PLA5: 99.82,151.89 99.82,163.7 109.73,163.7 109.73,156.08 132.59,156.08 132.59,151.89
GND_VID on PLA5: 31.88,153.8 31.88,161.42 22.73,161.42 22.73,158.88 14.73,158.88 14.73,164.34 25.53,164.34 25.53,168.15 29.34,168.15 29.34,199.52 24.89,199.52 24.89,231.27 8.38,231.27 8.38,244.35 16.38,244.35 16.38,236.09 24.26,236.09 24.26,243.08 41.78,243.08 41.78,236.73 48.13,236.73 48.13,234.19 61.72,234.19 61.72,237.36 68.07,237.36 68.07,243.71 77.34,243.71 77.34,231.9 38.61,231.9 38.61,199.52 34.8,199.52 34.8,163.7 48.13,163.7 48.13,157.61 36.07,157.61 36.07,153.8
Net_1 on PLA5: 219.84,202.06 219.84,224.66 239.9,224.66 239.9,219.84 224.66,219.84 224.66,202.06
Net_2 on PLA11 (solid shape): 207.52,231.01 241.81,231.01 241.81,203.96 238.25,203.96 238.25,224.92 201.42,224.92 201.42,232.92 207.52,232.92
Net_3 on PLA2 (solid shape): 170.69,210.95 165.23,210.95 165.23,223.01 163.32,223.01 163.32,226.57 170.69,226.57
Net_4 on PLA2 (solid shape): 157.99,215.39 149.35,215.39 149.35,225.93 157.99,225.93
Net_54 on PLA2: 96.01,119.51 96.01,135.76 104.27,135.76 104.27,151 123.06,151 123.06,148.72 119.25,148.72 119.25,147.45 116.08,147.45 116.08,146.81 111.63,146.81 111.63,119.51
Net_55 on PLA2: 96.01,119.51 96.01,135.76 104.27,135.76 104.27,151 123.06,151 123.06,148.72 119.25,148.72 119.25,147.45 116.08,147.45 116.08,146.81 111.63,146.81 111.63,119.51
Net_56 on PLA2: 96.01,119.51 96.01,135.76 104.27,135.76 104.27,151 123.06,151 123.06,148.72 119.25,148.72 119.25,147.45 116.08,147.45 116.08,146.81 111.63,146.81 111.63,119.51
Net_57 on PLA2: 212.22,147.45 212.22,149.35 161.42,149.35 161.42,161.24 166.42,166.24 224.66,166.24 224.66,163.07 239.9,163.07 239.9,158.62 247.78,158.62 247.78,163.7 276.86,163.7 276.86,149.99 249.68,149.99 249.68,153.8 227.2,153.8 227.2,147.45
Net_58 on PLA2: 226.82,14.73 226.82,71.88 209.68,71.88 209.68,116.97 198.88,116.97 198.88,129.41 216.03,129.41 216.03,132.21 210.06,132.21 210.06,130.94 206.5,130.94 206.5,139.57 209.68,139.57 209.68,145.54 201.17,145.54 201.17,142.37 168.15,142.37 168.15,134.75 148.72,134.75 148.72,149.1 211.96,149.1 211.96,147.19 227.46,147.19 227.46,153.54 249.43,153.54 249.43,41.15 252.6,41.15 252.6,36.32 250.06,36.32 250.06,29.08 252.6,29.08 252.6,14.73
Net_59 on PLA2: 212.22,147.45 212.22,149.35 161.42,149.35 161.42,161.24 166.42,166.24 224.66,166.24 224.66,163.07 239.9,163.07 239.9,158.62 247.78,158.62 247.78,163.7 276.86,163.7 276.86,149.99 249.68,149.99 249.68,153.8 227.2,153.8 227.2,147.45
Net_60 on PLA2: 226.82,14.73 226.82,71.88 209.68,71.88 209.68,116.97 198.88,116.97 198.88,129.41 216.03,129.41 216.03,132.21 210.06,132.21 210.06,130.94 206.5,130.94 206.5,139.57 209.68,139.57 209.68,145.54 201.17,145.54 201.17,142.37 168.15,142.37 168.15,134.75 148.72,134.75 148.72,149.1 211.96,149.1 211.96,147.19 227.46,147.19 227.46,153.54 249.43,153.54 249.43,41.15 252.6,41.15 252.6,36.32 250.06,36.32 250.06,29.08 252.6,29.08 252.6,14.73
Net_61 on PLA2: 212.22,147.45 212.22,149.35 161.42,149.35 161.42,161.24 166.42,166.24 224.66,166.24 224.66,163.07 239.9,163.07 239.9,158.62 247.78,158.62 247.78,163.7 276.86,163.7 276.86,149.99 249.68,149.99 249.68,153.8 227.2,153.8 227.2,147.45
Net_62 on PLA2: 226.82,14.73 226.82,71.88 209.68,71.88 209.68,116.97 198.88,116.97 198.88,129.41 216.03,129.41 216.03,132.21 210.06,132.21 210.06,130.94 206.5,130.94 206.5,139.57 209.68,139.57 209.68,145.54 201.17,145.54 201.17,142.37 168.15,142.37 168.15,134.75 148.72,134.75 148.72,149.1 211.96,149.1 211.96,147.19 227.46,147.19 227.46,153.54 249.43,153.54 249.43,41.15 252.6,41.15 252.6,36.32 250.06,36.32 250.06,29.08 252.6,29.08 252.6,14.73
Net_63 on PLA2: 39.5,136.65 39.5,157.35 40.77,157.35 40.77,168.78 67.44,168.78 67.44,178.94 70.99,178.94 70.99,136.65
Net_64 on PLA2: 209.68,2.54 209.68,29.97 21.08,29.97 21.08,107.19 111.89,107.19 111.89,146.56 116.33,146.56 116.33,147.19 119.51,147.19 119.51,148.46 123.06,148.46 123.06,147.83 137.29,147.83 137.29,149.1 148.46,149.1 148.46,134.49 168.4,134.49 168.4,142.11 201.42,142.11 201.42,145.29 209.42,145.29 209.42,139.83 206.25,139.83 206.25,130.68 210.31,130.68 210.31,131.95 215.77,131.95 215.77,129.67 198.63,129.67 198.63,116.71 209.42,116.71 209.42,71.63 226.57,71.63 226.57,14.48 252.86,14.48 252.86,29.34 250.32,29.34 250.32,36.07 252.86,36.07 252.86,41.4 249.68,41.4 249.68,149.73 276.86,149.73 276.86,2.54
Net_65 on PLA2: 39.5,136.65 39.5,157.35 40.77,157.35 40.77,168.78 67.44,168.78 67.44,178.94 70.99,178.94 70.99,136.65
Net_66 on PLA2: 209.68,2.54 209.68,29.97 21.08,29.97 21.08,107.19 111.89,107.19 111.89,146.56 116.33,146.56 116.33,147.19 119.51,147.19 119.51,148.46 123.06,148.46 123.06,147.83 137.29,147.83 137.29,149.1 148.46,149.1 148.46,134.49 168.4,134.49 168.4,142.11 201.42,142.11 201.42,145.29 209.42,145.29 209.42,139.83 206.25,139.83 206.25,130.68 210.31,130.68 210.31,131.95 215.77,131.95 215.77,129.67 198.63,129.67 198.63,116.71 209.42,116.71 209.42,71.63 226.57,71.63 226.57,14.48 252.86,14.48 252.86,29.34 250.32,29.34 250.32,36.07 252.86,36.07 252.86,41.4 249.68,41.4 249.68,149.73 276.86,149.73 276.86,2.54
Net_67 on PLA2: 39.5,136.65 39.5,157.35 40.77,157.35 40.77,168.78 67.44,168.78 67.44,178.94 70.99,178.94 70.99,136.65
Net_68 on PLA2: 209.68,2.54 209.68,29.97 21.08,29.97 21.08,107.19 111.89,107.19 111.89,146.56 116.33,146.56 116.33,147.19 119.51,147.19 119.51,148.46 123.06,148.46 123.06,147.83 137.29,147.83 137.29,149.1 148.46,149.1 148.46,134.49 168.4,134.49 168.4,142.11 201.42,142.11 201.42,145.29 209.42,145.29 209.42,139.83 206.25,139.83 206.25,130.68 210.31,130.68 210.31,131.95 215.77,131.95 215.77,129.67 198.63,129.67 198.63,116.71 209.42,116.71 209.42,71.63 226.57,71.63 226.57,14.48 252.86,14.48 252.86,29.34 250.32,29.34 250.32,36.07 252.86,36.07 252.86,41.4 249.68,41.4 249.68,149.73 276.86,149.73 276.86,2.54
Net_69 on PLA2: 165.23,210.95 165.23,223.01 163.32,223.01 163.32,226.57 170.69,226.57 170.69,210.95
Net_70 on PLA2: 165.23,210.95 165.23,223.01 163.32,223.01 163.32,226.57 170.69,226.57 170.69,210.95
Net_71 on PLA2: 165.23,210.95 165.23,223.01 163.32,223.01 163.32,226.57 170.69,226.57 170.69,210.95
Net_72 on PLA2: 149.35,215.39 149.35,225.93 157.99,225.93 157.99,215.39
Net_73 on PLA2: 134.11,148.08 134.11,157.61 123.32,157.61 123.32,161.42 122.05,161.42 122.05,163.96 119.51,163.96 119.51,168.4 113.16,168.4 113.16,174.5 123.7,174.5 123.7,170.05 136.02,170.05 136.02,175.13 151.82,175.13 156.97,180.29 156.97,203.71 191.26,203.71 191.26,211.96 198.25,211.96 198.25,229.11 206.5,229.11 206.5,248.16 229.11,248.16 229.11,244.98 254.51,244.98 254.51,240.16 251.33,240.16 251.33,227.2 276.86,227.2 276.86,163.96 247.52,163.96 247.52,158.88 240.16,158.88 240.16,163.32 224.92,163.32 224.92,166.5 166.32,166.5 161.16,161.34 161.16,149.35 137.03,149.35 137.03,148.08
Net_74 on PLA2: 2.54,2.54 2.54,251.46 276.86,251.46 276.86,227.46 251.59,227.46 251.59,239.9 254.76,239.9 254.76,245.24 229.36,245.24 229.36,248.41 206.38,248.41 206.29,248.37 206.25,248.28 206.25,229.36 197.99,229.36 197.99,212.22 191.01,212.22 191.01,203.96 156.72,203.96 156.72,180.39 151.71,175.39 135.76,175.39 135.76,170.31 123.95,170.31 123.95,174.75 112.9,174.75 112.9,168.15 119.25,168.15 119.25,163.7 121.79,163.7 121.79,161.16 123.06,161.16 123.06,157.35 133.86,157.35 133.86,148.08 123.32,148.08 123.32,151.26 104.01,151.26 104.01,136.02 95.76,136.02 95.76,119.25 111.63,119.25 111.63,107.44 20.83,107.44 20.83,29.72 209.42,29.72 209.42,2.54 ; 3 cut-outs
Net_75 on PLA2: 149.35,215.39 149.35,225.93 157.99,225.93 157.99,215.39
Net_76 on PLA2: 134.11,148.08 134.11,157.61 123.32,157.61 123.32,161.42 122.05,161.42 122.05,163.96 119.51,163.96 119.51,168.4 113.16,168.4 113.16,174.5 123.7,174.5 123.7,170.05 136.02,170.05 136.02,175.13 151.82,175.13 156.97,180.29 156.97,203.71 191.26,203.71 191.26,211.96 198.25,211.96 198.25,229.11 206.5,229.11 206.5,248.16 229.11,248.16 229.11,244.98 254.51,244.98 254.51,240.16 251.33,240.16 251.33,227.2 276.86,227.2 276.86,163.96 247.52,163.96 247.52,158.88 240.16,158.88 240.16,163.32 224.92,163.32 224.92,166.5 166.32,166.5 161.16,161.34 161.16,149.35 137.03,149.35 137.03,148.08
Net_77 on PLA2: 2.54,2.54 2.54,251.46 276.86,251.46 276.86,227.46 251.59,227.46 251.59,239.9 254.76,239.9 254.76,245.24 229.36,245.24 229.36,248.41 206.38,248.41 206.29,248.37 206.25,248.28 206.25,229.36 197.99,229.36 197.99,212.22 191.01,212.22 191.01,203.96 156.72,203.96 156.72,180.39 151.71,175.39 135.76,175.39 135.76,170.31 123.95,170.31 123.95,174.75 112.9,174.75 112.9,168.15 119.25,168.15 119.25,163.7 121.79,163.7 121.79,161.16 123.06,161.16 123.06,157.35 133.86,157.35 133.86,148.08 123.32,148.08 123.32,151.26 104.01,151.26 104.01,136.02 95.76,136.02 95.76,119.25 111.63,119.25 111.63,107.44 20.83,107.44 20.83,29.72 209.42,29.72 209.42,2.54 ; 3 cut-outs
Net_78 on PLA2: 149.35,215.39 149.35,225.93 157.99,225.93 157.99,215.39
Net_79 on PLA2: 134.11,148.08 134.11,157.61 123.32,157.61 123.32,161.42 122.05,161.42 122.05,163.96 119.51,163.96 119.51,168.4 113.16,168.4 113.16,174.5 123.7,174.5 123.7,170.05 136.02,170.05 136.02,175.13 151.82,175.13 156.97,180.29 156.97,203.71 191.26,203.71 191.26,211.96 198.25,211.96 198.25,229.11 206.5,229.11 206.5,248.16 229.11,248.16 229.11,244.98 254.51,244.98 254.51,240.16 251.33,240.16 251.33,227.2 276.86,227.2 276.86,163.96 247.52,163.96 247.52,158.88 240.16,158.88 240.16,163.32 224.92,163.32 224.92,166.5 166.32,166.5 161.16,161.34 161.16,149.35 137.03,149.35 137.03,148.08
Net_80 on PLA2: 2.54,2.54 2.54,251.46 276.86,251.46 276.86,227.46 251.59,227.46 251.59,239.9 254.76,239.9 254.76,245.24 229.36,245.24 229.36,248.41 206.38,248.41 206.29,248.37 206.25,248.28 206.25,229.36 197.99,229.36 197.99,212.22 191.01,212.22 191.01,203.96 156.72,203.96 156.72,180.39 151.71,175.39 135.76,175.39 135.76,170.31 123.95,170.31 123.95,174.75 112.9,174.75 112.9,168.15 119.25,168.15 119.25,163.7 121.79,163.7 121.79,161.16 123.06,161.16 123.06,157.35 133.86,157.35 133.86,148.08 123.32,148.08 123.32,151.26 104.01,151.26 104.01,136.02 95.76,136.02 95.76,119.25 111.63,119.25 111.63,107.44 20.83,107.44 20.83,29.72 209.42,29.72 209.42,2.54 ; 3 cut-outs
Net_81 on PLA5: 50.93,234.44 50.93,237.36 54.74,237.36 54.74,243.71 61.47,243.71 61.47,234.44
SHIELD on PLA5, PLA8: 48.39,234.44 48.39,236.98 42.04,236.98 42.04,243.33 24,243.33 24,236.35 16.64,236.35 16.64,251.46 83.06,251.46 83.06,236.35 77.6,236.35 77.6,243.97 67.82,243.97 67.82,237.62 61.72,237.62 61.72,243.97 54.48,243.97 54.48,237.62 50.67,237.62 50.67,234.44
V_1V5 on PLA2 (solid shape): 224.66,163.07 239.9,163.07 239.9,158.62 247.78,158.62 247.78,163.7 276.86,163.7 276.86,149.99 249.68,149.99 249.68,153.8 227.2,153.8 227.2,147.45 212.22,147.45 212.22,149.35 161.42,149.35 161.42,161.24 166.42,166.24 224.66,166.24
V_1V5 on PLA11 (solid shape): 126.87,158.62 207.14,158.62 207.14,162.43 227.2,162.43 227.2,147.45 93.34,147.45 93.26,147.41 93.22,147.32 93.22,133.48 30.61,133.48 30.61,144.27 27.43,144.27 27.43,146.56 32.89,146.56 32.89,136.4 90.3,136.4 90.3,151 93.34,151 93.43,151.04 93.47,151.13 93.47,180.21 126.87,180.21
V_1V8 on PLA2 (solid shape): 123.06,148.72 119.25,148.72 119.25,147.45 116.08,147.45 116.08,146.81 111.63,146.81 111.63,119.51 96.01,119.51 96.01,135.76 104.27,135.76 104.27,151 123.06,151
V_3V3 on PLA2 (solid shape): outline of 91 points within 2.54,2.54 276.86,251.46
V_3V3 on PLA11 (solid shape): outline of 101 points within 2.54,2.54 276.86,251.46
V_CLK on PLA11 (solid shape): 138.94,211.58 136.4,211.58 136.4,188.09 110.62,188.09 110.62,197.99 114.81,197.99 114.81,191.01 125.22,191.01 125.22,195.45 133.48,195.45 133.48,200.15 122.43,200.15 122.43,197.61 118.24,197.61 118.24,209.42 133.48,209.42 133.48,213.87 138.94,213.87
V_CLKA on PLA11 (solid shape): 121.79,209.68 117.98,209.68 117.98,197.36 122.68,197.36 122.68,199.9 133.22,199.9 133.22,195.71 124.97,195.71 124.97,191.26 115.06,191.26 115.06,198.25 110.62,198.25 110.62,211.96 115.06,211.96 115.06,214.5 121.79,214.5
V_CORE on PLA2 (solid shape): 229.11,244.98 254.51,244.98 254.51,240.16 251.33,240.16 251.33,227.2 276.86,227.2 276.86,163.96 247.52,163.96 247.52,158.88 240.16,158.88 240.16,163.32 224.92,163.32 224.92,166.5 166.32,166.5 161.16,161.34 161.16,149.35 137.03,149.35 137.03,148.08 134.11,148.08 134.11,157.61 123.32,157.61 123.32,161.42 122.05,161.42 122.05,163.96 119.51,163.96 119.51,168.4 113.16,168.4 113.16,174.5 123.7,174.5 123.7,170.05 136.02,170.05 136.02,175.13 151.82,175.13 156.97,180.29 156.97,203.71 191.26,203.71 191.26,211.96 198.25,211.96 198.25,229.11 206.5,229.11 206.5,248.16 229.11,248.16
V_DDR on PLA2 (solid shape): 276.86,2.54 209.68,2.54 209.68,29.97 21.08,29.97 21.08,107.19 111.89,107.19 111.89,146.56 116.33,146.56 116.33,147.19 119.51,147.19 119.51,148.46 123.06,148.46 123.06,147.83 137.29,147.83 137.29,149.1 148.46,149.1 148.46,134.49 168.4,134.49 168.4,142.11 201.42,142.11 201.42,145.29 209.42,145.29 209.42,139.83 206.25,139.83 206.25,130.68 210.31,130.68 210.31,131.95 215.77,131.95 215.77,129.67 198.63,129.67 198.63,116.71 209.42,116.71 209.42,71.63 226.57,71.63 226.57,14.48 252.86,14.48 252.86,29.34 250.32,29.34 250.32,36.07 252.86,36.07 252.86,41.4 249.68,41.4 249.68,149.73 276.86,149.73
V_DDRVTT on PLA2 (solid shape): 249.43,41.15 252.6,41.15 252.6,36.32 250.06,36.32 250.06,29.08 252.6,29.08 252.6,14.73 226.82,14.73 226.82,71.88 209.68,71.88 209.68,116.97 198.88,116.97 198.88,129.41 216.03,129.41 216.03,132.21 210.06,132.21 210.06,130.94 206.5,130.94 206.5,139.57 209.68,139.57 209.68,145.54 201.17,145.54 201.17,142.37 168.15,142.37 168.15,134.75 148.72,134.75 148.72,149.1 211.96,149.1 211.96,147.19 227.46,147.19 227.46,153.54 249.43,153.54
V_VDD1 on PLA11 (solid shape): 67.18,168.4 57.15,168.4 57.06,168.36 57.02,168.27 57.02,158.88 54.48,158.88 54.48,144.27 40.13,144.27 40.13,168.15 51.44,168.15 51.52,168.19 51.56,168.27 51.56,172.59 62.36,172.59 62.36,178.94 67.18,178.94
V_VDD2 on PLA2 (solid shape): 70.99,136.65 39.5,136.65 39.5,157.35 40.77,157.35 40.77,168.78 67.44,168.78 67.44,178.94 70.99,178.94
V_VDD3 on PLA11 (solid shape): 76.07,163.96 70.99,163.96 70.99,136.65 53.47,136.65 53.47,144.02 54.74,144.02 54.74,158.62 57.28,158.62 57.28,168.15 70.61,168.15 70.61,172.59 76.07,172.59
